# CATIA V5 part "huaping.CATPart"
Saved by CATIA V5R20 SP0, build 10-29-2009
Part number: 花瓶
Material "White": density 7860 kg/m3, Young's modulus 2e+11 Pa, Poisson ratio 0.266
Material "Light Green": density 7860 kg/m3, Young's modulus 2e+11 Pa, Poisson ratio 0.266
Material "Fire Red": density 7860 kg/m3, Young's modulus 2e+11 Pa, Poisson ratio 0.266
Material "DS Dark Green": density 7860 kg/m3, Young's modulus 2e+11 Pa, Poisson ratio 0.266
Material "Crisp Blue": density 7860 kg/m3, Young's modulus 2e+11 Pa, Poisson ratio 0.266
Material "Crisp Orange": density 7860 kg/m3, Young's modulus 2e+11 Pa, Poisson ratio 0.266
Bounding box of the stored display mesh (mm): x -44.415 to 32.874, y -31.464 to 54.596, z -0.598 to 98.197
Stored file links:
  C:\Users\GBH\Desktop\180511415郭柏宏\huaping.CATPart
  D:\CATIAR20\win_b64\startup\materials\Catalog.CATMaterial
  D:\CATIAR20\win_b64\startup\materials\green_env_512x512.jpg
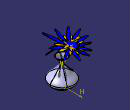
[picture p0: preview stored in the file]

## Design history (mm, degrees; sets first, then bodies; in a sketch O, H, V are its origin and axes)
Body1 (main body)
  Plane1: type Offset, RefPlane xy-plane, Offset 15
  Plane2: type Offset, RefPlane Plane1, Offset 15
  Sketch1 on xy-plane, origin (0, 0, 0), H (1, 0, 0), V (0, 1, 0)
    circle A1 centre (0, 0) radius 12.5
    radius A1 = 12.5
  Sketch2 on Plane1, origin (0, 0, 15), H (1, 0, 0), V (0, 1, 0)
    circle A1 centre (0, 0) radius 27.5
    radius A1 = 27.5
  Sketch3 on Plane2, origin (0, 0, 30), H (1, 0, 0), V (0, 1, 0)
    circle A1 centre (0, 0) radius 15
    radius A1 = 15
  Plane3: type Offset, RefPlane Plane2, Offset 15
  Sketch4 on Plane3, origin (0, 0, 45), H (1, 0, 0), V (0, 1, 0)
    circle A1 centre (0, 0) radius 5
    radius A1 = 5
  Plane4: type Offset, RefPlane Plane3, Offset 15
  Sketch5 on Plane4, origin (0, 0, 60), H (1, 0, 0), V (0, 1, 0)
    circle A1 centre (0, 0) radius 12.5
    radius A1 = 12.5
  Loft1: solid, Sections (Sketch5; Sketch4; Sketch3; Sketch2; Sketch1)
  Shell1: IntOffset 1, Face face of Loft1, ExtOffset 0
Body2, material "White"
  Sketch6 on yz-plane, origin (0, 0, 0), H (0, 1, 0), V (0, 0, 1)
  Sketch7 on yz-plane, origin (0, 0, 0), H (0, 1, 0), V (0, 0, 1)
    axis line L1 (0, -10) -> (0, 70)
    vertical: L1 V
  Sketch8 on yz-plane, origin (0, 0, 0), H (0, 1, 0), V (0, 0, 1)
    line L1 (0, 0) -> (0, 15.1169)
    line L2 (0, 15.1169) -> (27.5844, 15.1169)
    line L3 (27.5844, 15.1169) -> (25.3868, 9.6776)
    line L4 (25.3868, 9.6776) -> (21.2845, 5.1203)
    line L5 (21.2845, 5.1203) -> (15.2776, 1.592)
    line L6 (15.2776, 1.592) -> (12.5672, 0)
    point P6 (12.5672, 0)
    line L7 (12.5672, 0) -> (0, 0)
    vertical: L1 V
    horizontal: L2 H, L7 H
    parallelism: L6 L5
    coincidence: P6 H
  Shaft1: profile Sketch8, axis Sketch8.L1, angle 360
Body3, material "Light Green"
  Sketch9 on yz-plane, origin (0, 0, 0), H (0, 1, 0), V (0, 0, 1)
    spline S1 through (0, 0) (-5.401, 24.6496) (0, 45.5162) (-11.0887, 70.8414)
    point P1 (0, 0)
    point P2 (0, 45.5162)
    coincidence: P1 O, P2 V
  Plane5: type Normal, Curve Sketch9, RefPoint vertex of Sketch9
  Circle1: type CtrRad, Start 0, End 180, Center vertex of Sketch9, Support Plane5, Radius 1, FirstDirection (1, 0, 0)
  Rib1: profile Circle1, centre curve Sketch9
Body4, material "Fire Red"
  Sketch10 on Plane5, origin (0, -41.3866, 36.2585), H (1, 0, 0), V (0, 0.659, 0.7522)
    spline S1 through (0, 45.5851) (-13.5429, 56.7035) (-14.7741, 69.3661) (-2.7701, 61.0273) (0, 45.5851)
    point P1 (0, 45.5851)
    point P2 (0, 45.5851)
    coincidence: P1 V, P2 P1
  Pad1: profile Sketch10, direction (0, -0.7522, 0.659), length 1
  Sketch11 on Plane5, origin (0, -41.3866, 36.2585), H (1, 0, 0), V (0, 0.659, 0.7522)
    spline S1 through (0, 45.7395) (6.1559, 60.7184) (16.6208, 67.3586) (13.5429, 55.6225) (0, 45.7395)
    point P1 (0, 45.7395)
    point P2 (0, 45.7395)
    coincidence: P1 V, P2 P1
  Pad2: profile Sketch11, direction (0, -0.7522, 0.659), length 1
  Sketch12 on Plane5, origin (0, -41.3866, 36.2585), H (1, 0, 0), V (0, 0.659, 0.7522)
    spline S1 through (0, 45.7395) (-14.928, 50.0633) (-26.1624, 45.7395) (-14.928, 40.6436) (0, 45.7395)
    point P1 (0, 45.7395)
    point P2 (0, 45.7395)
    coincidence: P1 V, P2 P1
  Pad3: profile Sketch12, direction (0, -0.7522, 0.659), length 1
  Sketch13 on Plane5, origin (0, -41.3866, 36.2585), H (1, 0, 0), V (0, 0.659, 0.7522)
    spline S1 through (0, 44.9674) (-14.0046, 38.1728) (-15.5436, 26.7456) (-5.0786, 31.6871) (0, 44.9674)
    point P1 (0, 44.9674)
    point P2 (0, 44.9674)
    coincidence: P1 V, P2 P1
  Pad4: profile Sketch13, direction (0, -0.7522, 0.659), length 1
  Sketch14 on Plane5, origin (0, -41.3866, 36.2585), H (1, 0, 0), V (0, 0.659, 0.7522)
    spline S1 through (0, 45.8939) (1.6929, 32.4592) (16.7747, 30.2973) (12.7734, 41.7245) (0, 45.8939)
    point P1 (0, 45.8939)
    point P2 (0, 45.8939)
    coincidence: P1 V, P2 P1
  Pad5: profile Sketch14, direction (0, -0.7522, 0.659), length 1
Body5, material "DS Dark Green"
  Sketch15 on yz-plane, origin (0, 0, 0), H (0, 1, 0), V (0, 0, 1)
    spline S1 through (2.7024, 0) (7.3193, 27.7316) (2.7024, 43.3282) (12.0901, 71.2785) (18.7076, 89.037)
    point P1 (2.7024, 0)
    coincidence: P1 H
  Plane6: type Normal, Curve Sketch15, RefPoint vertex of Sketch15
  Circle2: type CtrRad, Start 0, End 180, Center vertex of Sketch15, Support Plane6, Radius 1, FirstDirection (1, 0, 0)
  Rib2: profile Circle2, centre curve Sketch15
Body6, material "Crisp Blue"
  Sketch16 on Plane6, origin (0, 16.392, 89.4613), H (1, 0, 0), V (0, -0.9836, 0.1802)
    spline S1 through (0, -1.8111) (5.0108, 26.4056) (14.4594, 48.4477) (11.5962, 26.4056) (0, -1.8111)
    point P1 (0, -1.8111)
    point P2 (0, -1.8111)
    coincidence: P1 V, P2 P1
  Pad6: profile Sketch16, direction (0, -0.1802, -0.9836), length 1
  Sketch17 on Plane6, origin (0, 16.392, 89.4613), H (1, 0, 0), V (0, -0.9836, 0.1802)
    spline S1 through (0, -2.0671) (-0.9491, 21.1289) (-9.1732, 42.5051) (-6.776, 19.5294) (0, -2.0671)
    point P1 (0, -2.0671)
    point P2 (0, -2.0671)
    coincidence: P1 V, P2 P1
  Pad7: profile Sketch17, direction (0, -0.1802, -0.9836), length 1
  Sketch18 on Plane6, origin (0, 16.392, 89.4613), H (1, 0, 0), V (0, -0.9836, 0.1802)
    spline S1 through (0, -1.3886) (-12.3153, 18.624) (-31.9009, 33.5537) (-16.692, 13.1728) (0, -1.3886)
    point P1 (0, -1.3886)
    point P2 (0, -1.3886)
    coincidence: P1 V, P2 P1
  Pad8: profile Sketch18, direction (0, -0.1802, -0.9836), length 1
  Sketch19 on Plane6, origin (0, 16.392, 89.4613), H (1, 0, 0), V (0, -0.9836, 0.1802)
    spline S1 through (0, -1.1843) (-17.2549, 9.8947) (-44.3984, 17.5696) (-19.2875, 4.8395) (0, -1.1843)
    point P1 (0, -1.1843)
    point P2 (0, -1.1843)
    coincidence: P1 V, P2 P1
  Pad9: profile Sketch19, direction (0, -0.1802, -0.9836), length 1
  Sketch20 on Plane6, origin (0, 16.392, 89.4613), H (1, 0, 0), V (0, -0.9836, 0.1802)
    spline S1 through (1.1298, 0.8327) (-25.6119, 1.4607) (-43.7049, -1.9358) (-25.6119, -4.8704) (1.1298, 0.8327)
    point P1 (1.1298, 0.8327)
    point P2 (1.1298, 0.8327)
    coincidence: P1 P2
  Pad10: profile Sketch20, direction (0, -0.1802, -0.9836), length 1
  Sketch21 on Plane6, origin (0, 16.392, 89.4613), H (1, 0, 0), V (0, -0.9836, 0.1802)
    spline S1 through (0, -1.66) (-18.9105, -8.251) (-35.3356, -17.7557) (-15.7354, -12.0919) (0, -1.66)
    point P1 (0, -1.66)
    point P2 (0, -1.66)
    coincidence: P1 V, P2 P1
  Pad11: profile Sketch21, direction (0, -0.1802, -0.9836), length 1
  Sketch22 on Plane6, origin (0, 16.392, 89.4613), H (1, 0, 0), V (0, -0.9836, 0.1802)
    spline S1 through (0, -1.7379) (-13.6123, -13.7716) (-22.7251, -31.4404) (-9.3233, -17.5511) (0, -1.7379)
    point P1 (0, -1.7379)
    point P2 (0, -1.7379)
    coincidence: P1 V, P2 P1
  Pad12: profile Sketch22, direction (0, -0.1802, -0.9836), length 1
  Sketch23 on Plane6, origin (0, 16.392, 89.4613), H (1, 0, 0), V (0, -0.9836, 0.1802)
    spline S1 through (-0.4666, -2.0349) (-7.3726, -20.5205) (-10.5545, -38.837) (-1.6372, -22.117) (-0.4666, -2.0349)
    point P1 (-0.4666, -2.0349)
    point P2 (-0.4666, -2.0349)
    coincidence: P1 P2
  Pad13: profile Sketch23, direction (0, -0.1802, -0.9836), length 1
  Sketch24 on Plane6, origin (0, 16.392, 89.4613), H (1, 0, 0), V (0, -0.9836, 0.1802)
    spline S1 through (-0.5135, -2.0708) (3.8877, -22.688) (10.2985, -37.6653) (9.5351, -21.3596) (-0.5135, -2.0708)
    point P1 (-0.5135, -2.0708)
    point P2 (-0.5135, -2.0708)
    coincidence: P1 P2
  Pad14: profile Sketch24, direction (0, -0.1802, -0.9836), length 1
  Sketch25 on Plane6, origin (0, 16.392, 89.4613), H (1, 0, 0), V (0, -0.9836, 0.1802)
    spline S1 through (0, -2.3259) (14.8511, -13.699) (32.816, -21.4841) (16.322, -8.7007) (0, -2.3259)
    point P1 (0, -2.3259)
    point P2 (0, -2.3259)
    coincidence: P1 V, P2 P1
  Pad15: profile Sketch25, direction (0, -0.1802, -0.9836), length 1
  Sketch26 on Plane6, origin (0, 16.392, 89.4613), H (1, 0, 0), V (0, -0.9836, 0.1802)
    spline S1 through (0, -1.9062) (11.4384, 7.8582) (31.277, 15.1993) (12.7867, 0) (0, -1.9062)
    point P1 (0, -1.9062)
    point P2 (12.7867, 0)
    point P3 (0, -1.9062)
    coincidence: P1 V, P2 H, P3 P1
  Pad16: profile Sketch26, direction (0, -0.1802, -0.9836), length 1
Body7, material "Crisp Orange"
  Sketch27 on Plane6, origin (0, 16.392, 89.4613), H (1, 0, 0), V (0, -0.9836, 0.1802)
    spline S1 through (0, -1.4597) (13.0162, 1.8679) (24.3239, -0.5267) (11.4629, -5.108) (0, -1.4597)
    spline S2 through (0, -1.4597) (-19.1904, 6.512) (-30.9824, 5.0449) (-21.1334, 0) (0, -1.4597)
    point P1 (0, -1.4597)
    point P2 (0, -1.4597)
    point P3 (0, -1.4597)
    point P4 (-21.1334, 0)
    point P5 (0, -1.4597)
    coincidence: P1 V, P2 P1, P3 P1, P4 H, P5 P1
  Pad17: profile Sketch27, direction (0, -0.1802, -0.9836), length 1
  Sketch28 on Plane6, origin (0, 16.392, 89.4613), H (1, 0, 0), V (0, -0.9836, 0.1802)
    spline S1 through (0, -1.7428) (8.8368, -8.4225) (15.0135, -18.0649) (4.6195, -12.3258) (0, -1.7428)
    point P1 (0, -1.7428)
    point P2 (0, -1.7428)
    coincidence: P1 V, P2 P1
  Pad18: profile Sketch28, direction (0, -0.1802, -0.9836), length 1
  Sketch29 on Plane6, origin (0, 16.392, 89.4613), H (1, 0, 0), V (0, -0.9836, 0.1802)
    spline S1 through (0, -2.1225) (3.3242, -15.9707) (2.1578, -25.5847) (-2.5216, -15.1515) (0, -2.1225)
    point P1 (0, -2.1225)
    point P2 (0, -2.1225)
    coincidence: P1 V, P2 P1
  Pad19: profile Sketch29, direction (0, -0.1802, -0.9836), length 1
  Sketch30 on Plane6, origin (0, 16.392, 89.4613), H (1, 0, 0), V (0, -0.9836, 0.1802)
    spline S1 through (0, -2.1417) (-4.4341, -16.3457) (-11.0267, -25.5157) (-8.2378, -12.4719) (0, -2.1417)
    point P1 (0, -2.1417)
    point P2 (0, -2.1417)
    coincidence: P1 V, P2 P1
  Pad20: profile Sketch30, direction (0, -0.1802, -0.9836), length 1
  Sketch31 on Plane6, origin (0, 16.392, 89.4613), H (1, 0, 0), V (0, -0.9836, 0.1802)
    spline S1 through (0, -2.0787) (-9.1198, -11.6147) (-19.3649, -16.8975) (-9.1198, -6.9269) (0, -2.0787)
    point P1 (0, -2.0787)
    point P2 (0, -2.0787)
    coincidence: P1 V, P2 P1
  Pad21: profile Sketch31, direction (0, -0.1802, -0.9836), length 1
  Sketch32 on Plane6, origin (0, 16.392, 89.4613), H (1, 0, 0), V (0, -0.9836, 0.1802)
    spline S1 through (0, -2.4594) (-16.6966, -2.4594) (-27.6698, -6.6244) (-16.6966, -9.2251) (0, -2.4594)
    point P1 (0, -2.4594)
    point P2 (0, -2.4594)
    coincidence: P1 V, P2 P1
  Pad22: profile Sketch32, direction (0, -0.1802, -0.9836), length 1
  Sketch33 on Plane6, origin (0, 16.392, 89.4613), H (1, 0, 0), V (0, -0.9836, 0.1802)
    spline S1 through (0, -2.8259) (10.0067, 3.9008) (17.7889, 17.1415) (5.3288, 7.8993) (0, -2.8259)
    point P1 (0, -2.8259)
    point P2 (0, -2.8259)
    coincidence: P1 V, P2 P1
  Pad23: profile Sketch33, direction (0, -0.1802, -0.9836), length 1
  Sketch34 on Plane6, origin (0, 16.392, 89.4613), H (1, 0, 0), V (0, -0.9836, 0.1802)
    spline S1 through (0, -2.4063) (2.9197, 10.4881) (2.3018, 24.6475) (-1.4041, 11.2512) (0, -2.4063)
    point P1 (0, -2.4063)
    point P2 (0, -2.4063)
    coincidence: P1 V, P2 P1
  Pad24: profile Sketch34, direction (0, -0.1802, -0.9836), length 1
  Sketch35 on Plane6, origin (0, 16.392, 89.4613), H (1, 0, 0), V (0, -0.9836, 0.1802)
    spline S1 through (0, -1.6721) (-3.6715, 12.887) (-10.3203, 22.9496) (-8.0837, 9.7062) (0, -1.6721)
    point P1 (0, -1.6721)
    point P2 (0, -1.6721)
    coincidence: P1 V, P2 P1
  Pad25: profile Sketch35, direction (0, -0.1802, -0.9836), length 1
  Sketch36 on Plane6, origin (0, 16.392, 89.4613), H (1, 0, 0), V (0, -0.9836, 0.1802)
    spline S1 through (-0.4852, -1.5291) (-9.4286, 9.6845) (-21.7195, 15.8248) (-13.4553, 5.3529) (-0.4852, -1.5291)
    point P1 (-0.4852, -1.5291)
    point P2 (-0.4852, -1.5291)
    coincidence: P1 P2
  Pad26: profile Sketch36, direction (0, -0.1802, -0.9836), length 1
